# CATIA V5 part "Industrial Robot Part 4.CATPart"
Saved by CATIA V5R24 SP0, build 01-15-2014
Part number: Industrial Robot Part 4
Source: Unknown
Material "Metal Blue": density 7860 kg/m3, Young's modulus 2e+11 Pa, Poisson ratio 0.266
Bounding box of the stored display mesh (mm): x 185.181 to 261.148, y -293.478 to 188.767, z -208.943 to 145.719
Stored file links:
  C:\Users\cdl\Downloads\2024_CAD_final\p2\Industrial Robot Part 4.CATPart
  D:\Program Files\Dassault Systemes\B24\win_b64\startup\materials\Catalog.CATMaterial
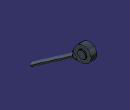
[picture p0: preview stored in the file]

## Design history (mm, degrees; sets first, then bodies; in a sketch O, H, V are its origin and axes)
Set1 "Reference Datas"
  Plane1 "Middle Plane": type Normal, Curve {line type PtPt, FirstPoint {point type Center, Curve edge [face of Solid1 | face of Solid1]}, SecondPoint {point type Center, Curve edge [face of Solid1 | face of Solid1]}}
Body1 (main body), material "Metal Blue"
  Solid1 "Solid 1": solid without history
  Translate1: Direction (0, 0, 1), Length -656, ToTransfor Solid1
  Translate2: Direction (0, 1, 0), Length 240, ToTransfor Translate1
  Rotate1: Axis Y axis, Angle 221, ToTransfor Translate2
  Rotate2: Axis Z axis, Angle 272, ToTransfor Rotate1
  Translate3: Direction (1, 0, 0), Length 230, ToTransfor Rotate2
